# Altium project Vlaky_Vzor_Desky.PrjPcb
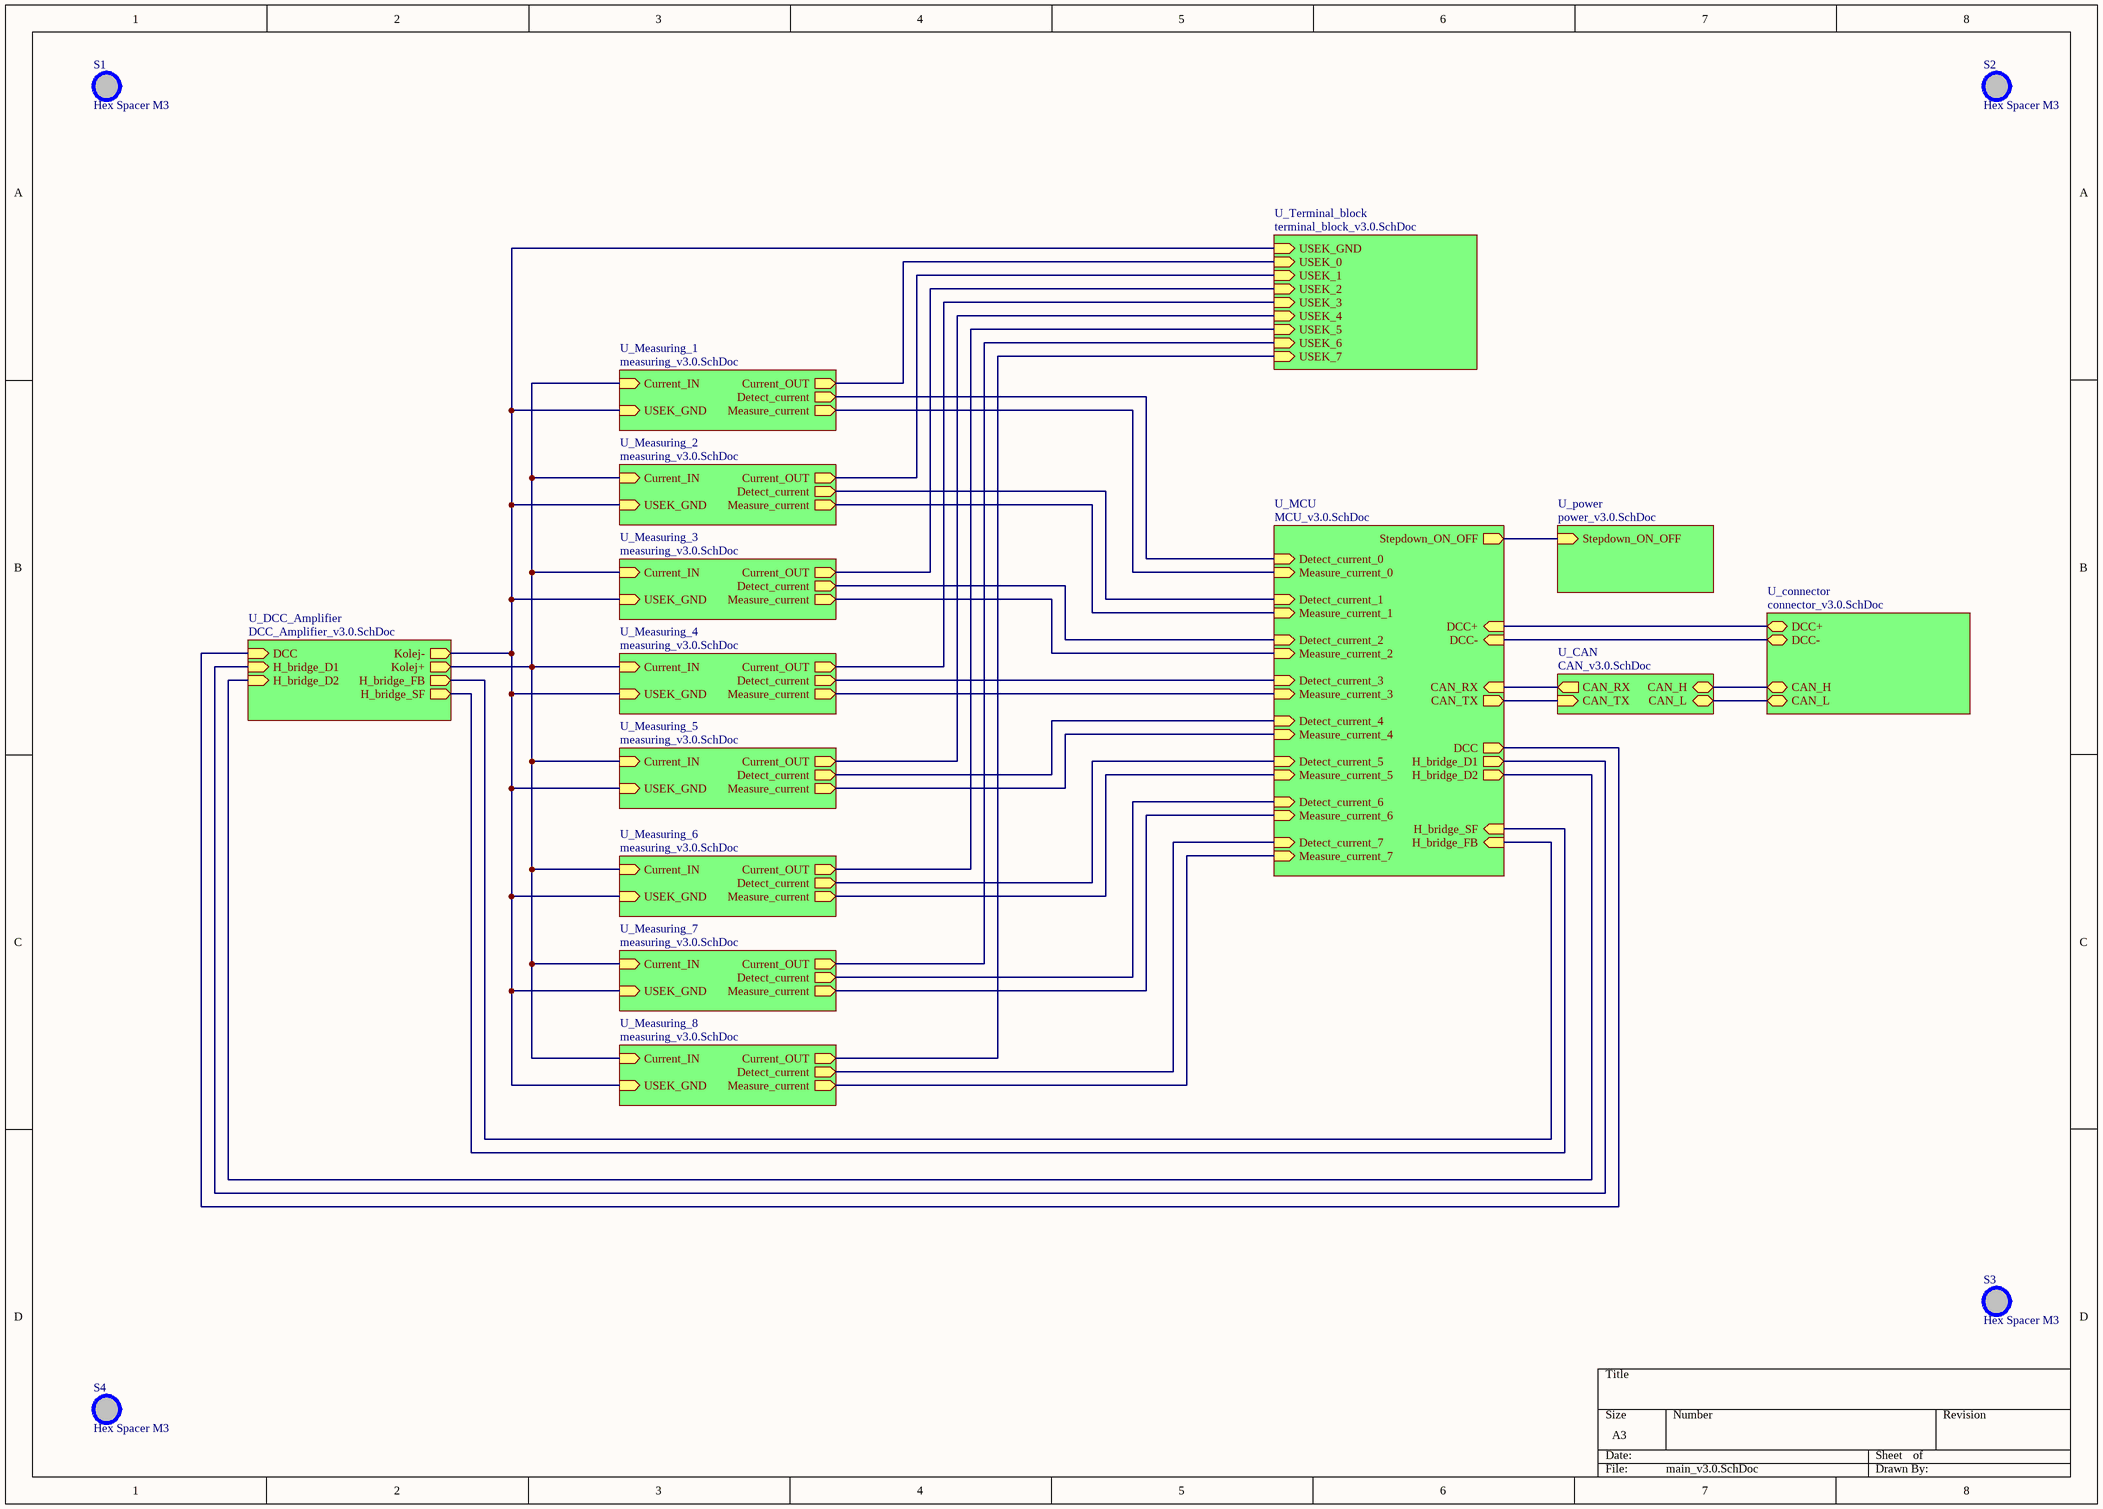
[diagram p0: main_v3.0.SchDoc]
10 sheets, 283 parts. Net scope: hierarchical (ports join the sheet entries above them; power ports are global).
Board file: PCB_v3.0.PcbDoc
Sheets:
  main_v3.0.SchDoc
    U_CAN = CAN_v3.0.SchDoc
    U_DCC_Amplifier = DCC_Amplifier_v3.0.SchDoc
    U_Terminal_block = terminal_block_v3.0.SchDoc
    U_MCU = MCU_v3.0.SchDoc
    U_power = power_v3.0.SchDoc
    U_connector = connector_v3.0.SchDoc
    U_Measuring_1 = measuring_v3.0.SchDoc
      U_Detect_current = detect_current_v3.0.SchDoc
      U_Measure_current = measure_current_v3.0.SchDoc
    U_Measuring_2 = measuring_v3.0.SchDoc
      U_Detect_current = detect_current_v3.0.SchDoc
      U_Measure_current = measure_current_v3.0.SchDoc
    U_Measuring_3 = measuring_v3.0.SchDoc
      U_Detect_current = detect_current_v3.0.SchDoc
      U_Measure_current = measure_current_v3.0.SchDoc
    U_Measuring_4 = measuring_v3.0.SchDoc
      U_Detect_current = detect_current_v3.0.SchDoc
      U_Measure_current = measure_current_v3.0.SchDoc
    U_Measuring_5 = measuring_v3.0.SchDoc
      U_Detect_current = detect_current_v3.0.SchDoc
      U_Measure_current = measure_current_v3.0.SchDoc
    U_Measuring_6 = measuring_v3.0.SchDoc
      U_Detect_current = detect_current_v3.0.SchDoc
      U_Measure_current = measure_current_v3.0.SchDoc
    U_Measuring_7 = measuring_v3.0.SchDoc
      U_Detect_current = detect_current_v3.0.SchDoc
      U_Measure_current = measure_current_v3.0.SchDoc
    U_Measuring_8 = measuring_v3.0.SchDoc
      U_Detect_current = detect_current_v3.0.SchDoc
      U_Measure_current = measure_current_v3.0.SchDoc

## Sheet main_v3.0.SchDoc
size A3; DocumentNumber: 1; SheetNumber: 1; SheetTotal: 10

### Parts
S1  Hex Spacer M3  [THT_HEX_SPACER_M3L20]
S2  Hex Spacer M3  [THT_HEX_SPACER_M3L20]
S3  Hex Spacer M3  [THT_HEX_SPACER_M3L20]
S4  Hex Spacer M3  [THT_HEX_SPACER_M3L20]

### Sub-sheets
U_CAN = CAN_v3.0.SchDoc: CAN_H (bidir), CAN_L (bidir), CAN_TX (in), CAN_RX (out)
U_connector = connector_v3.0.SchDoc: CAN_H (bidir), CAN_L (bidir), DCC+ (bidir), DCC- (bidir)
U_DCC_Amplifier = DCC_Amplifier_v3.0.SchDoc: DCC (in), Kolej- (out), Kolej+ (out), H_bridge_D1 (in), H_bridge_D2 (in), H_bridge_FB (out), H_bridge_SF (out)
U_MCU = MCU_v3.0.SchDoc: DCC- (in), DCC (out), Stepdown_ON_OFF (out), H_bridge_SF (in), H_bridge_D1 (out), H_bridge_D2 (out), H_bridge_FB (in), Measure_current_0 (in), Detect_current_0 (in), Detect_current_1 (in), DCC+ (in), CAN_TX (out), CAN_RX (in), Detect_current_2 (in), Detect_current_3 (in), Detect_current_4 (in), Detect_current_5 (in), Detect_current_6 (in), Detect_current_7 (in), Measure_current_1 (in), Measure_current_2 (in), Measure_current_3 (in), Measure_current_4 (in), Measure_current_5 (in), Measure_current_6 (in), Measure_current_7 (in)
U_Measuring_1 = measuring_v3.0.SchDoc: Current_IN (in), Measure_current (out), Detect_current (out), Current_OUT (out), USEK_GND (in)
U_Measuring_2 = measuring_v3.0.SchDoc: Current_IN (in), Measure_current (out), Detect_current (out), Current_OUT (out), USEK_GND (in)
U_Measuring_3 = measuring_v3.0.SchDoc: Current_IN (in), Measure_current (out), Detect_current (out), Current_OUT (out), USEK_GND (in)
U_Measuring_4 = measuring_v3.0.SchDoc: Current_IN (in), Measure_current (out), Detect_current (out), Current_OUT (out), USEK_GND (in)
U_Measuring_5 = measuring_v3.0.SchDoc: Current_IN (in), Measure_current (out), Detect_current (out), Current_OUT (out), USEK_GND (in)
U_Measuring_6 = measuring_v3.0.SchDoc: Current_IN (in), Measure_current (out), Detect_current (out), Current_OUT (out), USEK_GND (in)
U_Measuring_7 = measuring_v3.0.SchDoc: Current_IN (in), Measure_current (out), Detect_current (out), Current_OUT (out), USEK_GND (in)
U_Measuring_8 = measuring_v3.0.SchDoc: Current_IN (in), Measure_current (out), Detect_current (out), Current_OUT (out), USEK_GND (in)
U_power = power_v3.0.SchDoc: Stepdown_ON_OFF (in)
U_Terminal_block = terminal_block_v3.0.SchDoc: USEK_0 (in), USEK_GND (in), USEK_1 (in), USEK_2 (in), USEK_3 (in), USEK_4 (in), USEK_5 (in), USEK_6 (in), USEK_7 (in)

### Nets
CAN_H: sheet U_CAN/CAN_H, sheet U_connector/CAN_H
CAN_L: sheet U_CAN/CAN_L, sheet U_connector/CAN_L
CAN_RX: sheet U_CAN/CAN_RX, sheet U_MCU/CAN_RX
CAN_TX: sheet U_CAN/CAN_TX, sheet U_MCU/CAN_TX
DCC+: sheet U_MCU/DCC+, sheet U_connector/DCC+
DCC-: sheet U_MCU/DCC-, sheet U_connector/DCC-
NetC24.1_2: sheet U_DCC_Amplifier/Kolej-, sheet U_Terminal_block/USEK_GND, sheet U_Measuring_1/USEK_GND, sheet U_Measuring_2/USEK_GND, sheet U_Measuring_3/USEK_GND, sheet U_Measuring_4/USEK_GND, sheet U_Measuring_5/USEK_GND, sheet U_Measuring_6/USEK_GND, sheet U_Measuring_7/USEK_GND, sheet U_Measuring_8/USEK_GND
NetC27.1_2: sheet U_MCU/Measure_current_0, sheet U_Measuring_1/Measure_current
NetC27.2_2: sheet U_MCU/Measure_current_1, sheet U_Measuring_2/Measure_current
NetC27.3_2: sheet U_MCU/Measure_current_2, sheet U_Measuring_3/Measure_current
NetC27.4_2: sheet U_MCU/Measure_current_3, sheet U_Measuring_4/Measure_current
NetC27.5_2: sheet U_MCU/Measure_current_4, sheet U_Measuring_5/Measure_current
NetC27.6_2: sheet U_MCU/Measure_current_5, sheet U_Measuring_6/Measure_current
NetC27.7_2: sheet U_MCU/Measure_current_6, sheet U_Measuring_7/Measure_current
NetC27.8_2: sheet U_MCU/Measure_current_7, sheet U_Measuring_8/Measure_current
NetD12.1_2: sheet U_DCC_Amplifier/Kolej+, sheet U_Measuring_1/Current_IN, sheet U_Measuring_2/Current_IN, sheet U_Measuring_3/Current_IN, sheet U_Measuring_4/Current_IN, sheet U_Measuring_5/Current_IN, sheet U_Measuring_6/Current_IN, sheet U_Measuring_7/Current_IN, sheet U_Measuring_8/Current_IN
NetD17_1: sheet U_DCC_Amplifier/H_bridge_FB, sheet U_MCU/H_bridge_FB
NetIC1.1_3: sheet U_MCU/Detect_current_0, sheet U_Measuring_1/Detect_current
NetIC1.2_3: sheet U_MCU/Detect_current_1, sheet U_Measuring_2/Detect_current
NetIC1.3_3: sheet U_MCU/Detect_current_2, sheet U_Measuring_3/Detect_current
NetIC1.4_3: sheet U_MCU/Detect_current_3, sheet U_Measuring_4/Detect_current
NetIC1.5_3: sheet U_MCU/Detect_current_4, sheet U_Measuring_5/Detect_current
NetIC1.6_3: sheet U_MCU/Detect_current_5, sheet U_Measuring_6/Detect_current
NetIC1.7_3: sheet U_MCU/Detect_current_6, sheet U_Measuring_7/Detect_current
NetIC1.8_3: sheet U_MCU/Detect_current_7, sheet U_Measuring_8/Detect_current
NetP8_1: sheet U_Terminal_block/USEK_0, sheet U_Measuring_1/Current_OUT
NetP9_1: sheet U_Terminal_block/USEK_1, sheet U_Measuring_2/Current_OUT
NetP10_1: sheet U_Terminal_block/USEK_2, sheet U_Measuring_3/Current_OUT
NetP11_1: sheet U_Terminal_block/USEK_3, sheet U_Measuring_4/Current_OUT
NetP12_1: sheet U_Terminal_block/USEK_4, sheet U_Measuring_5/Current_OUT
NetP13_1: sheet U_Terminal_block/USEK_5, sheet U_Measuring_6/Current_OUT
NetP14_1: sheet U_Terminal_block/USEK_6, sheet U_Measuring_7/Current_OUT
NetP15_1: sheet U_Terminal_block/USEK_7, sheet U_Measuring_8/Current_OUT
NetR18_1: sheet U_DCC_Amplifier/H_bridge_D2, sheet U_MCU/H_bridge_D2
NetR22_2: sheet U_DCC_Amplifier/H_bridge_D1, sheet U_MCU/H_bridge_D1
NetR23_2: sheet U_MCU/Stepdown_ON_OFF, sheet U_power/Stepdown_ON_OFF
NetR32_1: sheet U_DCC_Amplifier/H_bridge_SF, sheet U_MCU/H_bridge_SF
NetU3_4: sheet U_DCC_Amplifier/DCC, sheet U_MCU/DCC

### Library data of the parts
S1-S4 = HEX_SPACER_M3: Hexagon metal spacer M3

## Sheet CAN_v3.0.SchDoc
size A4; DrawnBy: Lufinkao; DocumentNumber: 5; Revision: 11.4.2019; SheetNumber: 5; SheetTotal: 10
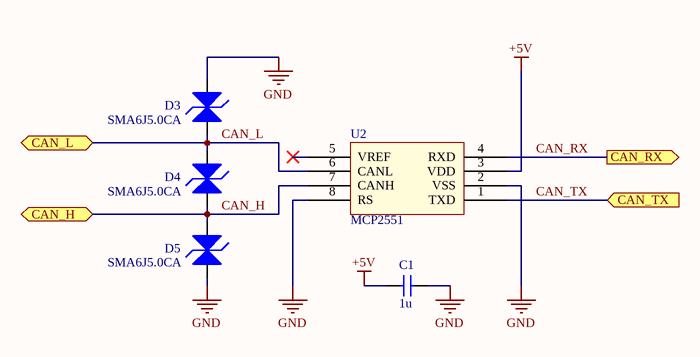
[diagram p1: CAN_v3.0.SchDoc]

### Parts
C1  1u  [SMD_CAPACITOR_0805]
D3  SMA6J5.0CA  [SMD_DO-214AC]
D4  SMA6J5.0CA  [SMD_DO-214AC]
D5  SMA6J5.0CA  [SMD_DO-214AC]
U2  MCP2551  [SMD_SOIC-8]

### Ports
CAN_H (bidir), CAN_L (bidir), CAN_RX (out), CAN_TX (in)

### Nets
+5V: C1.1 U2.3(VDD)
GND: C1.2 D3.2 D5.1 U2.2(VSS) U2.8(RS)
CAN_H: D4.1 D5.2 U2.7(CANH) ; port CAN_H
CAN_L: D3.1 D4.2 U2.6(CANL) ; port CAN_L
CAN_RX: U2.4(RXD) ; port CAN_RX
CAN_TX: U2.1(TXD) ; port CAN_TX

Not connected (* = marked no-connect by the designer): U2 5(VREF)*

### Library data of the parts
C1 = Capacitor
D3-D5 = Transil: Transient Voltage Suppressor, Bidirectional
U2 = MCP2551: CAN Transceiver, 4.5 V - 5.5 V, 1 Mb/s

## Sheet DCC_Amplifier_v3.0.SchDoc
size A3; DocumentNumber: 9; SheetNumber: 9; SheetTotal: 10
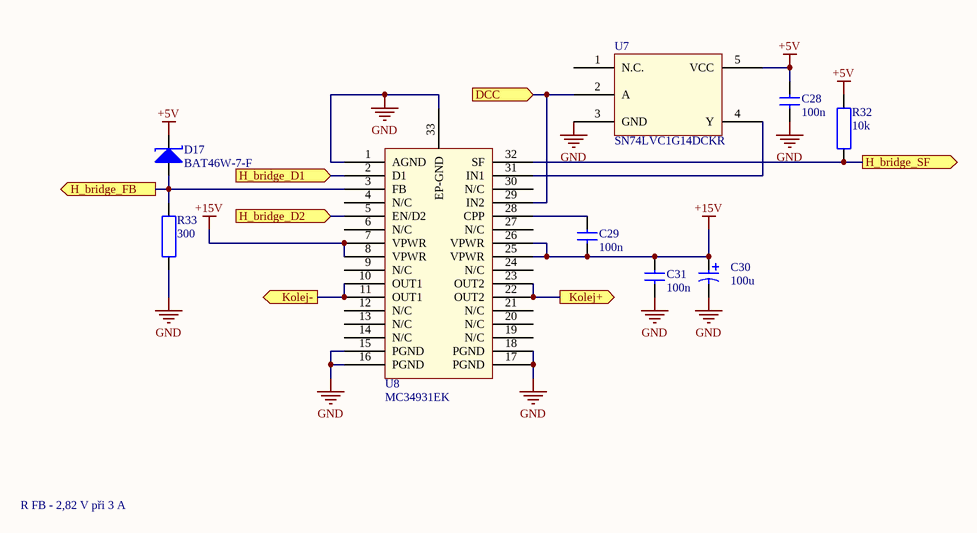
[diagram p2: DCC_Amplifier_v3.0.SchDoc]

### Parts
C28  100n  [SMD_CAPACITOR_0805]
C29  100n  [SMD_CAPACITOR_0805]
C30  100u  [SMD_CAPACITOR_D_6.3MM]
C31  100n  [SMD_CAPACITOR_0805]
D17  BAT46W-7-F  [SMD_SOD-123]
R32  10k  [SMD_RESISTOR_0805]
R33  300  [SMD_RESISTOR_0805]
U7  SN74LVC1G14DCKR  [SMD_SC-70-5]
U8  MC34931EK  [SMD_WSOIC32]

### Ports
DCC (in), H_bridge_D1 (in), H_bridge_D2 (in), H_bridge_FB (out), H_bridge_SF (out), Kolej+ (out), Kolej- (out)

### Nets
+5V: C28.2 D17.2 R32.2 U7.5(VCC)
+15V: C29.1 C30.1 C31.2 U8.7(VPWR) U8.8(VPWR) U8.25(VPWR) U8.26(VPWR)
GND: C28.1 C30.2 C31.1 R33.1 U7.3(GND) U8.1(AGND) U8.15(PGND) U8.16(PGND) U8.17(PGND) U8.18(PGND) U8.33(EP-GND)
NetC24.1_2: U8.10(OUT1) U8.11(OUT1) ; port Kolej-
NetC29_2: C29.2 U8.28(CPP)
NetD12.1_2: U8.22(OUT2) U8.23(OUT2) ; port Kolej+
NetD17_1: D17.1 R33.2 U8.3(FB) ; port H_bridge_FB
NetR18_1: U8.5(EN/D2) ; port H_bridge_D2
NetR22_2: U8.2(D1) ; port H_bridge_D1
NetR32_1: R32.1 U8.32(SF) ; port H_bridge_SF
NetU3_4: U7.2(A) U8.29(IN2) ; port DCC
NetU7_4: U7.4(Y) U8.31(IN1)

Not connected (* = marked no-connect by the designer): U7 1(N.C.); U8 4(N/C) 6(N/C) 9(N/C) 12(N/C) 13(N/C) 14(N/C) 19(N/C) 20(N/C) 21(N/C) 24(N/C) 27(N/C) 30(N/C)

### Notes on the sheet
- R FB - 2,82 V při 3 A

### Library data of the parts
C28 C29 C31 = Capacitor
C30 = Capacitor_POL
D17 = Diode_Schottky: Diode Schottky
R32 R33 = Resistor
U7 = SN74LVC1G14DCKR: Hradlo invertujici
U8 = MC34931EK: The MC34931EK is a monolithic H-bridge Power IC designed for any low voltage DC servo motor control application within the current and voltage limits stated in this specification.

## Sheet terminal_block_v3.0.SchDoc
size A3; DocumentNumber: 10; SheetNumber: 10; SheetTotal: 10
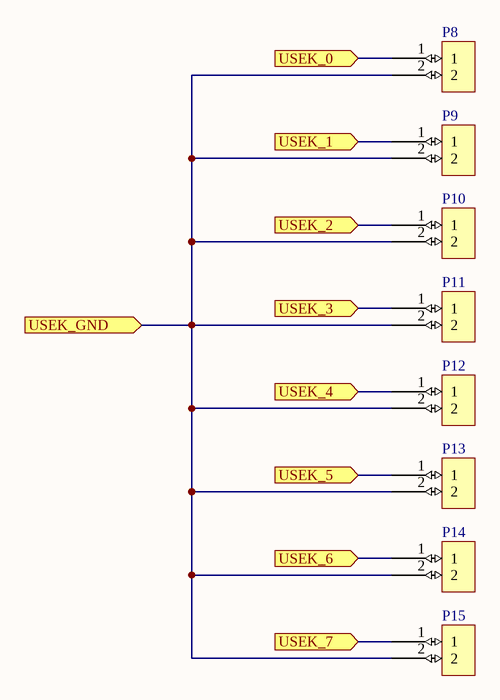
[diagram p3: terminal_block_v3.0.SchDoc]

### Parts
P8  End_Terminal_2pos_5.00mm  [Terminal_Block_2pos_5.00mm_pitch]  (value not drawn)
P9  End_Terminal_2pos_5.00mm  [Terminal_Block_2pos_5.00mm_pitch]  (value not drawn)
P10  End_Terminal_2pos_5.00mm  [Terminal_Block_2pos_5.00mm_pitch]  (value not drawn)
P11  End_Terminal_2pos_5.00mm  [Terminal_Block_2pos_5.00mm_pitch]  (value not drawn)
P12  End_Terminal_2pos_5.00mm  [Terminal_Block_2pos_5.00mm_pitch]  (value not drawn)
P13  End_Terminal_2pos_5.00mm  [Terminal_Block_2pos_5.00mm_pitch]  (value not drawn)
P14  End_Terminal_2pos_5.00mm  [Terminal_Block_2pos_5.00mm_pitch]  (value not drawn)
P15  End_Terminal_2pos_5.00mm  [Terminal_Block_2pos_5.00mm_pitch]  (value not drawn)

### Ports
USEK_0 (in), USEK_1 (in), USEK_2 (in), USEK_3 (in), USEK_4 (in), USEK_5 (in), USEK_6 (in), USEK_7 (in), USEK_GND (in)

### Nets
NetC24.1_2: P8.2 P9.2 P10.2 P11.2 P12.2 P13.2 P14.2 P15.2 ; port USEK_GND
NetP8_1: P8.1 ; port USEK_0
NetP9_1: P9.1 ; port USEK_1
NetP10_1: P10.1 ; port USEK_2
NetP11_1: P11.1 ; port USEK_3
NetP12_1: P12.1 ; port USEK_4
NetP13_1: P13.1 ; port USEK_5
NetP14_1: P14.1 ; port USEK_6
NetP15_1: P15.1 ; port USEK_7

## Sheet MCU_v3.0.SchDoc
size A4; DrawnBy: Lufinkao; DocumentNumber: 2; Revision: 11.4.2019; SheetNumber: 2; SheetTotal: 10
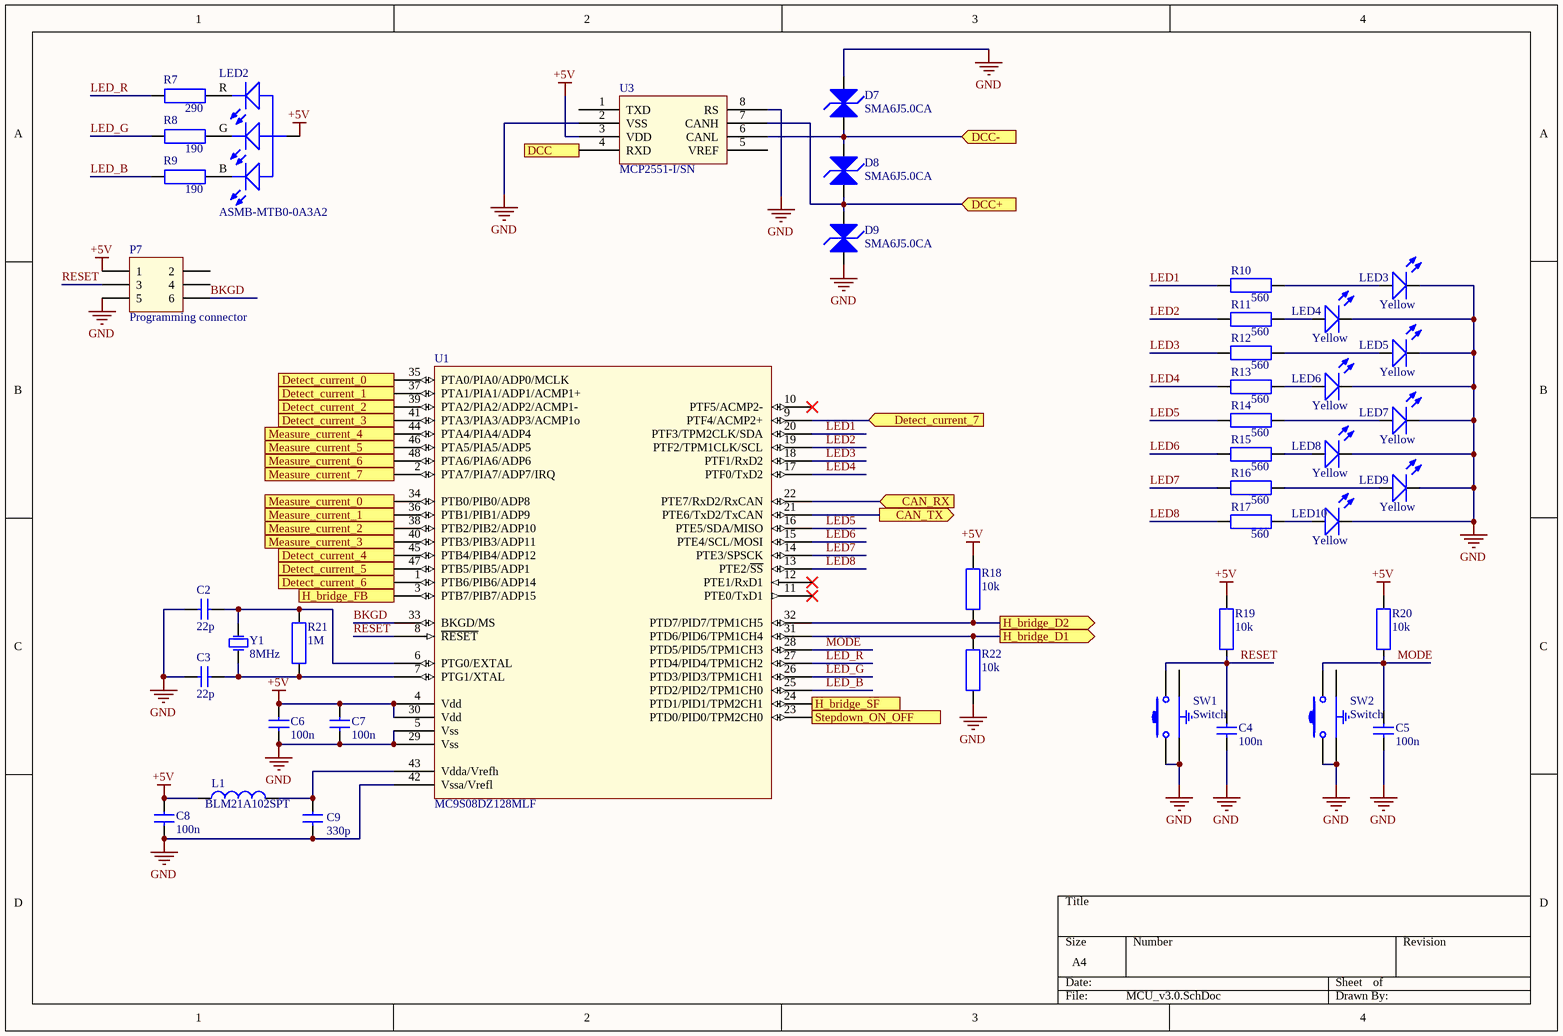
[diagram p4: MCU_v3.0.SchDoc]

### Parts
C2  22p  [SMD_CAPACITOR_0805]
C3  22p  [SMD_CAPACITOR_0805]
C4  100n  [SMD_CAPACITOR_0805]
C5  100n  [SMD_CAPACITOR_0805]
C6  100n  [SMD_CAPACITOR_0805]
C7  100n  [SMD_CAPACITOR_0805]
C8  100n  [SMD_CAPACITOR_0805]
C9  330p  [SMD_CAPACITOR_0805]
D7  SMA6J5.0CA  [SMD_DO-214AC]
D8  SMA6J5.0CA  [SMD_DO-214AC]
D9  SMA6J5.0CA  [SMD_DO-214AC]
L1  BLM21A102SPT  [SMD_INDUCTOR_0805]
LED2  ASMB-MTB0-0A3A2  [SMD_LED_RGB]
LED3  Yellow  [SMD_LED_0805]
LED4  Yellow  [SMD_LED_0805]
LED5  Yellow  [SMD_LED_0805]
LED6  Yellow  [SMD_LED_0805]
LED7  Yellow  [SMD_LED_0805]
LED8  Yellow  [SMD_LED_0805]
LED9  Yellow  [SMD_LED_0805]
LED10  Yellow  [SMD_LED_0805]
P7  Programming connector  [THT_HEADER_100MIL_2X3_MALE]
R7  290  [SMD_RESISTOR_0805]
R8  190  [SMD_RESISTOR_0805]
R9  190  [SMD_RESISTOR_0805]
R10  560  [SMD_RESISTOR_0805]
R11  560  [SMD_RESISTOR_0805]
R12  560  [SMD_RESISTOR_0805]
R13  560  [SMD_RESISTOR_0805]
R14  560  [SMD_RESISTOR_0805]
R15  560  [SMD_RESISTOR_0805]
R16  560  [SMD_RESISTOR_0805]
R17  560  [SMD_RESISTOR_0805]
R18  10k  [SMD_RESISTOR_0805]
R19  10k  [SMD_RESISTOR_0805]
R20  10k  [SMD_RESISTOR_0805]
R21  1M  [SMD_RESISTOR_0805]
R22  10k  [SMD_RESISTOR_0805]
SW1  Switch  [THT_SWITCH_SPST_90]
SW2  Switch  [THT_SWITCH_SPST_90]
U1  MC9S08DZ128MLF  [SMD_LQFP-48]
U3  MCP2551-I/SN  [SMD_SOIC-8]
Y1  8MHz  [SMD_XTAL_HC-49]

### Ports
CAN_RX (in), CAN_TX (out), DCC (out), DCC+ (in), DCC- (in), Detect_current_0 (in), Detect_current_1 (in), Detect_current_2 (in), Detect_current_3 (in), Detect_current_4 (in), Detect_current_5 (in), Detect_current_6 (in), Detect_current_7 (in), H_bridge_D1 (out), H_bridge_D2 (out), H_bridge_FB (in), H_bridge_SF (in), Measure_current_0 (in), Measure_current_1 (in), Measure_current_2 (in), Measure_current_3 (in), Measure_current_4 (in), Measure_current_5 (in), Measure_current_6 (in), Measure_current_7 (in), Stepdown_ON_OFF (out)

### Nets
+5V: C6.1 C7.1 C8.1 L1.1 LED2.1(ANODE) P7.1 R18.2 R19.2 R20.2 U1.4(Vdd) U1.30(Vdd) U3.3(VDD)
GND: C2.1 C3.1 C4.2 C5.2 C6.2 C7.2 C8.2 C9.1 D7.2 D9.1 LED3.2 LED4.2 LED5.2 LED6.2 LED7.2 LED8.2 LED9.2 LED10.2 P7.5 R22.1 SW1.1 SW1.3 SW2.1 SW2.3 U1.5(Vss) U1.29(Vss) U1.42(Vssa/Vrefl) U3.2(VSS) U3.8(RS)
BKGD: P7.6 U1.33(BKGD/MS)
CAN_RX: U1.22(PTE7/RxD2/RxCAN) ; port CAN_RX
CAN_TX: U1.21(PTE6/TxD2/TxCAN) ; port CAN_TX
DCC+: D8.1 D9.2 U3.7(CANH) ; port DCC+
DCC-: D7.1 D8.2 U3.6(CANL) ; port DCC-
LED1: R10.1 U1.20(PTF3/TPM2CLK/SDA)
LED2: R11.1 U1.19(PTF2/TPM1CLK/SCL)
LED3: R12.1 U1.18(PTF1/RxD2)
LED4: R13.1 U1.17(PTF0/TxD2)
LED5: R14.1 U1.16(PTE5/SDA/MISO)
LED6: R15.1 U1.15(PTE4/SCL/MOSI)
LED7: R16.1 U1.14(PTE3/SPSCK)
LED8: R17.1 U1.13(PTE2/~{SS})
LED_B: R9.2 U1.25(PTD2/PID2/TPM1CH0)
LED_G: R8.2 U1.26(PTD3/PID3/TPM1CH1)
LED_R: R7.2 U1.27(PTD4/PID4/TPM1CH2)
MODE: C5.1 R20.1 SW2.2 U1.28(PTD5/PID5/TPM1CH3)
RESET: C4.1 P7.3 R19.1 SW1.2 U1.8(~{RESET})
NetC2_2: C2.2 R21.2 U1.6(PTG0/EXTAL) Y1.2
NetC3_2: C3.2 R21.1 U1.7(PTG1/XTAL) Y1.1
NetC9_2: C9.2 L1.2 U1.43(Vdda/Vrefh)
NetC27.1_2: U1.34(PTB0/PIB0/ADP8) ; port Measure_current_0
NetC27.2_2: U1.36(PTB1/PIB1/ADP9) ; port Measure_current_1
NetC27.3_2: U1.38(PTB2/PIB2/ADP10) ; port Measure_current_2
NetC27.4_2: U1.40(PTB3/PIB3/ADP11) ; port Measure_current_3
NetC27.5_2: U1.44(PTA4/PIA4/ADP4) ; port Measure_current_4
NetC27.6_2: U1.46(PTA5/PIA5/ADP5) ; port Measure_current_5
NetC27.7_2: U1.48(PTA6/PIA6/ADP6) ; port Measure_current_6
NetC27.8_2: U1.2(PTA7/PIA7/ADP7/IRQ) ; port Measure_current_7
NetD17_1: U1.3(PTB7/PIB7/ADP15) ; port H_bridge_FB
NetIC1.1_3: U1.35(PTA0/PIA0/ADP0/MCLK) ; port Detect_current_0
NetIC1.2_3: U1.37(PTA1/PIA1/ADP1/ACMP1+) ; port Detect_current_1
NetIC1.3_3: U1.39(PTA2/PIA2/ADP2/ACMP1-) ; port Detect_current_2
NetIC1.4_3: U1.41(PTA3/PIA3/ADP3/ACMP1o) ; port Detect_current_3
NetIC1.5_3: U1.45(PTB4/PIB4/ADP12) ; port Detect_current_4
NetIC1.6_3: U1.47(PTB5/PIB5/ADP1) ; port Detect_current_5
NetIC1.7_3: U1.1(PTB6/PIB6/ADP14) ; port Detect_current_6
NetIC1.8_3: U1.9(PTF4/ACMP2+) ; port Detect_current_7
NetLED2_2: LED2.2(B) R9.1
NetLED2_3: LED2.3(G) R8.1
NetLED2_4: LED2.4(R) R7.1
NetLED3_1: LED3.1 R10.2
NetLED4_1: LED4.1 R11.2
NetLED5_1: LED5.1 R12.2
NetLED6_1: LED6.1 R13.2
NetLED7_1: LED7.1 R14.2
NetLED8_1: LED8.1 R15.2
NetLED9_1: LED9.1 R16.2
NetLED10_1: LED10.1 R17.2
NetR18_1: R18.1 U1.32(PTD7/PID7/TPM1CH5) ; port H_bridge_D2
NetR22_2: R22.2 U1.31(PTD6/PID6/TPM1CH4) ; port H_bridge_D1
NetR23_2: U1.23(PTD0/PID0/TPM2CH0) ; port Stepdown_ON_OFF
NetR32_1: U1.24(PTD1/PID1/TPM2CH1) ; port H_bridge_SF
NetU3_4: U3.4(RXD) ; port DCC

Not connected (* = marked no-connect by the designer): P7 2 4; SW1 4; SW2 4; U1 10(PTF5/ACMP2-)* 11(PTE0/TxD1)* 12(PTE1/RxD1)*; U3 1(TXD) 5(VREF)

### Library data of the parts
C2-C9 = Capacitor
D7-D9 = Transil: as D3 on sheet CAN_v3.0
L1 = Inductor
LED2 = LED_RGB: LED RGB
LED3-LED10 = LED
P7 = Header_2x3: Header 2x3
R7-R22 = Resistor
SW1 SW2 = Switch_90: Tactile Switch Right Angle
U1 = MC9S08DZ96: NXP 8 Bit Microcontroller, CAN
U3 = MCP2551: CAN Transceiver, 4.5 V - 5.5 V, 1 Mb/s
Y1 = XTAL: Crystal Oscillator

## Sheet power_v3.0.SchDoc
size A4; DrawnBy: Lufinkao; DocumentNumber: 4; Revision: 11.4.2019; SheetNumber: 4; SheetTotal: 10
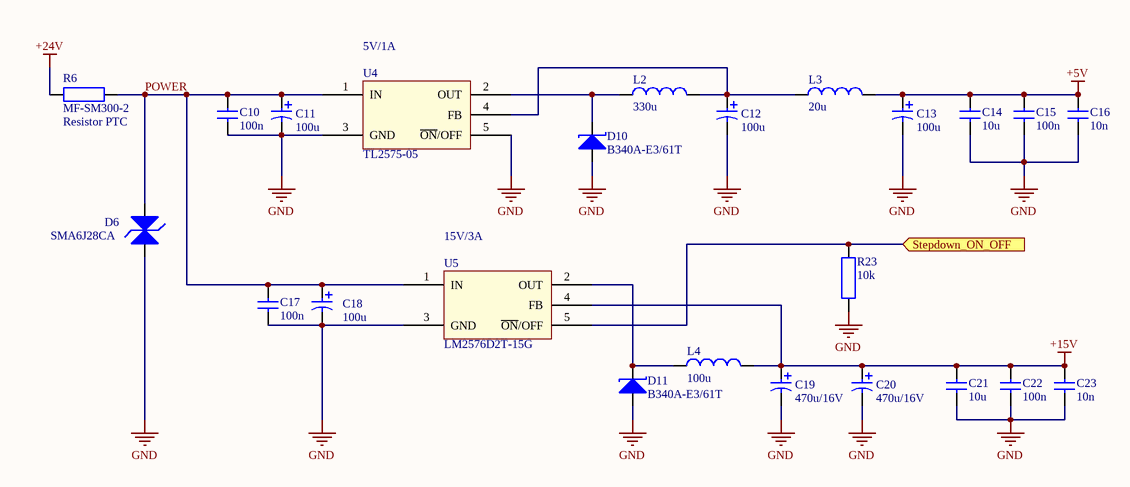
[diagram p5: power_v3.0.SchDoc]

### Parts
C10  value 100n  [SMD_CAPACITOR_0805]  (hidden comment: 10u)
C11  100u  [SMD_CAPACITOR_D_6.3MM]
C12  100u  [SMD_CAPACITOR_D_6.3MM]
C13  100u  [SMD_CAPACITOR_D_6.3MM]
C14  10u  [SMD_CAPACITOR_0805]
C15  100n  [SMD_CAPACITOR_0805]
C16  10n  [SMD_CAPACITOR_0805]
C17  value 100n  [SMD_CAPACITOR_0805]  (hidden comment: 10n)
C18  100u  [SMD_CAPACITOR_D_6.3MM]
C19  470u/16V  [SMD_CAPACITOR_D_10MM]
C20  470u/16V  [SMD_CAPACITOR_D_10MM]
C21  10u  [SMD_CAPACITOR_0805]
C22  100n  [SMD_CAPACITOR_0805]
C23  10n  [SMD_CAPACITOR_0805]
D6  SMA6J28CA  [SMD_DO-214AC]
D10  B340A-E3/61T  [SMD_DO-214AC]
D11  B340A-E3/61T  [SMD_DO-214AC]
L2  330u  [SMD_INDUCTOR_12.5MM]
L3  20u  [SMD_INDUCTOR_7.3MM]
L4  100u  [SMD_INDUCTOR_12.5MM]
R6  MF-SM300-2  [SMD_RESISTOR_PTC_MF-SM]
R23  10k  [SMD_RESISTOR_0805]
U4  TL2575-05  [SMD_TO-263-5]
U5  LM2576D2T-15G  [SMD_TO-263-5]

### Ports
Stepdown_ON_OFF (in)

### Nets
+5V: C13.1 C14.2 C15.2 C16.2 L3.2
+15V: C19.1 C20.1 C21.2 C22.2 C23.2 L4.2 U5.4(FB)
+24V: R6.1
GND: C10.1 C11.2 C12.2 C13.2 C14.1 C15.1 C16.1 C17.1 C18.2 C19.2 C20.2 C21.1 C22.1 C23.1 D6.1 D10.1 D11.1 R23.1 U4.3(GND) U4.5(~{ON}/OFF) U5.3(GND)
POWER: C10.2 C11.1 C17.2 C18.1 D6.2 R6.2 U4.1(IN) U5.1(IN)
NetC12_1: C12.1 L2.2 L3.1 U4.4(FB)
NetD10_2: D10.2 L2.1 U4.2(OUT)
NetD11_2: D11.2 L4.1 U5.2(OUT)
NetR23_2: R23.2 U5.5(~{ON}/OFF) ; port Stepdown_ON_OFF

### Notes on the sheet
- (near U4) 5V/1A
- (near U5) 15V/3A

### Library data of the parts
C10 C14-C17 C21-C23 = Capacitor
C11-C13 C18-C20 = Capacitor_POL
D6 = Transil: as D3 on sheet CAN_v3.0
D10 D11 = Diode_Schottky: Diode Schottky
L2-L4 = Inductor
R6 = Resistor_PTC: Resistor PTC
R23 = Resistor
U4 U5 = TL2575-05: Buck (Step Down) Switching Regulator, 4.75V-40V Input, 5 V, 1A Output

## Sheet connector_v3.0.SchDoc
size A4; DrawnBy: Lufinkao; DocumentNumber: 3; Revision: 11.4.2019; SheetNumber: 3; SheetTotal: 10
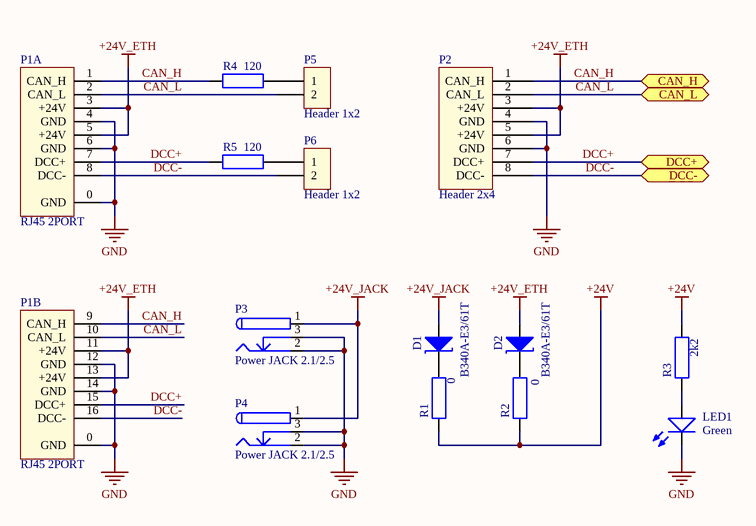
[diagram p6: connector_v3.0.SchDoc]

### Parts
D1  B340A-E3/61T  [SMD_DO-214AC]
D2  B340A-E3/61T  [SMD_DO-214AC]
LED1  Green  [THT_LED_3MM]
P1  RJ45 2PORT  [THT_RJ45_2PORT]  (parts A,B of 2)
P2  Header 2x4  [SMD_HEADER_100MIL_2X4_DOUBLESIDED]
P3  Power JACK 2.1/2.5  [THT_POWER_JACK_2.1/2.5]
P4  Power JACK 2.1/2.5  [THT_POWER_JACK_2.1/2.5]
P5  Header 1x2  [THT_HEADER_100MIL_1X2_MALE]
P6  Header 1x2  [THT_HEADER_100MIL_1X2_MALE]
R1  0  [SMD_RESISTOR_0805]
R2  0  [SMD_RESISTOR_0805]
R3  2k2  [SMD_RESISTOR_0805]
R4  120  [SMD_RESISTOR_0805]
R5  120  [SMD_RESISTOR_0805]

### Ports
CAN_H (bidir), CAN_L (bidir), DCC+ (bidir), DCC- (bidir)

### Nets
+24V: R1.1 R2.1 R3.2
+24V_ETH: D2.1 P1.3(+24V) P1.5(+24V) P1.11(+24V) P1.13(+24V) P2.3(+24V) P2.5(+24V)
+24V_JACK: D1.1 P3.1 P4.1
GND: LED1.2 P1.0(GND) P1.4(GND) P1.6(GND) P1.12(GND) P1.14(GND) P2.4(GND) P2.6(GND) P3.2 P3.3 P4.2 P4.3
CAN_H: P1.1(CAN_H) P1.9(CAN_H) P2.1(CAN_H) R4.2 ; port CAN_H
CAN_L: P1.2(CAN_L) P1.10(CAN_L) P2.2(CAN_L) P5.2 ; port CAN_L
DCC+: P1.7(DCC+) P1.15(DCC+) P2.7(DCC+) R5.2 ; port DCC+
DCC-: P1.8(DCC-) P1.16(DCC-) P2.8(DCC-) P6.2 ; port DCC-
NetD1_2: D1.2 R1.2
NetD2_2: D2.2 R2.2
NetLED1_1: LED1.1 R3.1
NetP5_1: P5.1 R4.1
NetP6_1: P6.1 R5.1

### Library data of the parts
D1 D2 = Diode_Schottky: Diode Schottky
LED1 = LED
P1 = RJ45_2PORT: RJ45 - 2 port; Objednací kód: RJHSE538002; Dodavatel: TME; Výrobce: AMPHENOL
P2 = Header_2x4_Trains_Project
P3 P4 = Power_JACK_2.1/2.5: Low Voltage Power Supply Connector
P5 P6 = Header_1x2
R1-R5 = Resistor

## Sheet measuring_v3.0.SchDoc
size A3; DocumentNumber: 6; SheetNumber: 6; SheetTotal: 8
Used 8 times, as channels U_Measuring_1, U_Measuring_2, U_Measuring_3, U_Measuring_4, U_Measuring_5, U_Measuring_6, U_Measuring_7, U_Measuring_8. Parts and nets are listed once, with the designators drawn on the sheet.
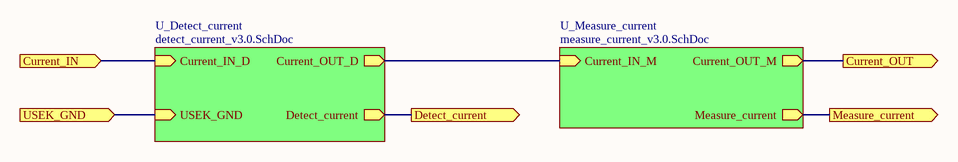
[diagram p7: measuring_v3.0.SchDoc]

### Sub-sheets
U_Detect_current = detect_current_v3.0.SchDoc: Current_IN_D (in), Current_OUT_D (out), Detect_current (out), USEK_GND (in)
U_Measure_current = measure_current_v3.0.SchDoc: Current_IN_M (in), Measure_current (out), Current_OUT_M (out)

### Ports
Current_IN (in), Current_OUT (out), Detect_current (out), Measure_current (out), USEK_GND (in)

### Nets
Current_IN: port Current_IN, sheet U_Detect_current/Current_IN_D
Current_OUT: port Current_OUT, sheet U_Measure_current/Current_OUT_M
Detect_current: port Detect_current, sheet U_Detect_current/Detect_current
Measure_current: port Measure_current, sheet U_Measure_current/Measure_current
USEK_GND: port USEK_GND, sheet U_Detect_current/USEK_GND
(unnamed): sheet U_Detect_current/Current_OUT_D, sheet U_Measure_current/Current_IN_M

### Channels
U_Measuring_1: ports Current_IN=NetD12.1_2 Current_OUT=NetP8_1 Detect_current=NetIC1.1_3 Measure_current=NetC27.1_2 USEK_GND=NetC24.1_2
U_Measuring_2: ports Current_IN=NetD12.1_2 Current_OUT=NetP9_1 Detect_current=NetIC1.2_3 Measure_current=NetC27.2_2 USEK_GND=NetC24.1_2
U_Measuring_3: ports Current_IN=NetD12.1_2 Current_OUT=NetP10_1 Detect_current=NetIC1.3_3 Measure_current=NetC27.3_2 USEK_GND=NetC24.1_2
U_Measuring_4: ports Current_IN=NetD12.1_2 Current_OUT=NetP11_1 Detect_current=NetIC1.4_3 Measure_current=NetC27.4_2 USEK_GND=NetC24.1_2
U_Measuring_5: ports Current_IN=NetD12.1_2 Current_OUT=NetP12_1 Detect_current=NetIC1.5_3 Measure_current=NetC27.5_2 USEK_GND=NetC24.1_2
U_Measuring_6: ports Current_IN=NetD12.1_2 Current_OUT=NetP13_1 Detect_current=NetIC1.6_3 Measure_current=NetC27.6_2 USEK_GND=NetC24.1_2
U_Measuring_7: ports Current_IN=NetD12.1_2 Current_OUT=NetP14_1 Detect_current=NetIC1.7_3 Measure_current=NetC27.7_2 USEK_GND=NetC24.1_2
U_Measuring_8: ports Current_IN=NetD12.1_2 Current_OUT=NetP15_1 Detect_current=NetIC1.8_3 Measure_current=NetC27.8_2 USEK_GND=NetC24.1_2

## Sheet detect_current_v3.0.SchDoc
size A3; DocumentNumber: 7; SheetNumber: 7; SheetTotal: 8
Used 8 times, as channels U_Measuring_1/U_Detect_current, U_Measuring_2/U_Detect_current, U_Measuring_3/U_Detect_current, U_Measuring_4/U_Detect_current, U_Measuring_5/U_Detect_current, U_Measuring_6/U_Detect_current, U_Measuring_7/U_Detect_current, U_Measuring_8/U_Detect_current. Parts and nets are listed once, with the designators drawn on the sheet.
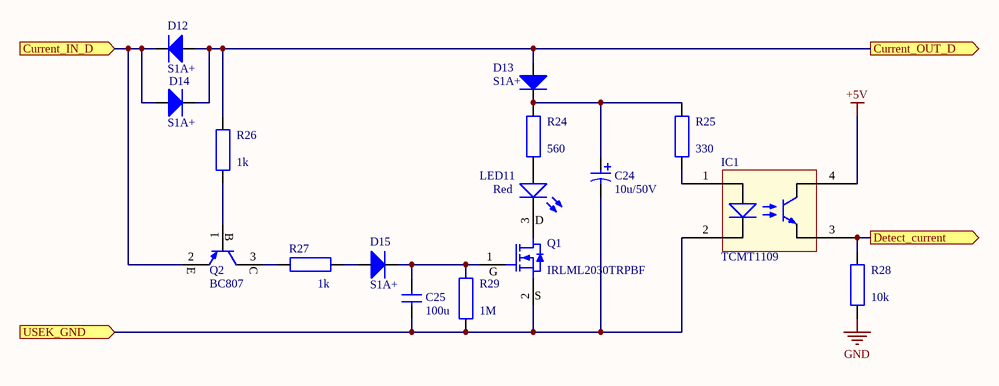
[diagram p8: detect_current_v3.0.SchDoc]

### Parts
C24  10u/50V  [SMD_CAPACITOR_D_6.3MM]
C25  100u  [SMD_CAPACITOR_0805]
D12  S1A+  [SMD_DO-214AC]
D13  S1A+  [SMD_DO-214AC]
D14  S1A+  [SMD_DO-214AC]
D15  S1A+  [SMD_DO-214AC]
IC1  TCMT1109  [TCMT110x]
LED11  Red  [SMD_LED_0805]
Q1  IRLML2030TRPBF  [SMD_SOT-23]
Q2  BC807  [SMD_SOT-23]
R24  560  [SMD_RESISTOR_0805]
R25  330  [SMD_RESISTOR_0805]
R26  1k  [SMD_RESISTOR_0805]
R27  1k  [SMD_RESISTOR_0805]
R28  10k  [SMD_RESISTOR_0805]
R29  1M  [SMD_RESISTOR_0805]

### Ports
Current_IN_D (in), Current_OUT_D (out), Detect_current (out), USEK_GND (in)

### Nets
+5V: IC1.4
GND: R28.1
Current_IN_D: D12.2 D14.1 Q2.2 ; port Current_IN_D
Current_OUT_D: D12.1 D13.1 D14.2 R26.2 ; port Current_OUT_D
Detect_current: IC1.3 R28.2 ; port Detect_current
USEK_GND: C24.2 C25.1 IC1.2 Q1.2 R29.1 ; port USEK_GND
NetC24_1: C24.1 D13.2 R24.2 R25.1
NetC25_2: C25.2 D15.2 Q1.1 R29.2
NetD15_1: D15.1 R27.1
NetIC1_1: IC1.1 R25.2
NetLED11_1: LED11.1 R24.1
NetLED11_2: LED11.2 Q1.3
NetQ2_1: Q2.1 R26.1
NetQ2_3: Q2.3 R27.2

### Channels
U_Measuring_1/U_Detect_current: designators C24=C24.1 C25=C25.1 D12=D12.1 D13=D13.1 D14=D14.1 D15=D15.1 IC1=IC1.1 LED11=LED11.1 Q1=Q1.1 Q2=Q2.1 R24=R25.1 R25=R26.1 R26=R27.1 R27=R28.1 R28=R29.1 R29=R30.1; ports Current_IN_D=NetD12.1_2 Current_OUT_D=NetD12.1_1 Detect_current=NetIC1.1_3 USEK_GND=NetC24.1_2
U_Measuring_2/U_Detect_current: designators C24=C24.2 C25=C25.2 D12=D12.2 D13=D13.2 D14=D14.2 D15=D15.2 IC1=IC1.2 LED11=LED11.2 Q1=Q1.2 Q2=Q2.2 R24=R25.2 R25=R26.2 R26=R27.2 R27=R28.2 R28=R29.2 R29=R30.2; ports Current_IN_D=NetD12.1_2 Current_OUT_D=NetD12.2_1 Detect_current=NetIC1.2_3 USEK_GND=NetC24.1_2
U_Measuring_3/U_Detect_current: designators C24=C24.3 C25=C25.3 D12=D12.3 D13=D13.3 D14=D14.3 D15=D15.3 IC1=IC1.3 LED11=LED11.3 Q1=Q1.3 Q2=Q2.3 R24=R25.3 R25=R26.3 R26=R27.3 R27=R28.3 R28=R29.3 R29=R30.3; ports Current_IN_D=NetD12.1_2 Current_OUT_D=NetD12.3_1 Detect_current=NetIC1.3_3 USEK_GND=NetC24.1_2
U_Measuring_4/U_Detect_current: designators C24=C24.4 C25=C25.4 D12=D12.4 D13=D13.4 D14=D14.4 D15=D15.4 IC1=IC1.4 LED11=LED11.4 Q1=Q1.4 Q2=Q2.4 R24=R25.4 R25=R26.4 R26=R27.4 R27=R28.4 R28=R29.4 R29=R30.4; ports Current_IN_D=NetD12.1_2 Current_OUT_D=NetD12.4_1 Detect_current=NetIC1.4_3 USEK_GND=NetC24.1_2
U_Measuring_5/U_Detect_current: designators C24=C24.5 C25=C25.5 D12=D12.5 D13=D13.5 D14=D14.5 D15=D15.5 IC1=IC1.5 LED11=LED11.5 Q1=Q1.5 Q2=Q2.5 R24=R25.5 R25=R26.5 R26=R27.5 R27=R28.5 R28=R29.5 R29=R30.5; ports Current_IN_D=NetD12.1_2 Current_OUT_D=NetD12.5_1 Detect_current=NetIC1.5_3 USEK_GND=NetC24.1_2
U_Measuring_6/U_Detect_current: designators C24=C24.6 C25=C25.6 D12=D12.6 D13=D13.6 D14=D14.6 D15=D15.6 IC1=IC1.6 LED11=LED11.6 Q1=Q1.6 Q2=Q2.6 R24=R25.6 R25=R26.6 R26=R27.6 R27=R28.6 R28=R29.6 R29=R30.6; ports Current_IN_D=NetD12.1_2 Current_OUT_D=NetD12.6_1 Detect_current=NetIC1.6_3 USEK_GND=NetC24.1_2
U_Measuring_7/U_Detect_current: designators C24=C24.7 C25=C25.7 D12=D12.7 D13=D13.7 D14=D14.7 D15=D15.7 IC1=IC1.7 LED11=LED11.7 Q1=Q1.7 Q2=Q2.7 R24=R25.7 R25=R26.7 R26=R27.7 R27=R28.7 R28=R29.7 R29=R30.7; ports Current_IN_D=NetD12.1_2 Current_OUT_D=NetD12.7_1 Detect_current=NetIC1.7_3 USEK_GND=NetC24.1_2
U_Measuring_8/U_Detect_current: designators C24=C24.8 C25=C25.8 D12=D12.8 D13=D13.8 D14=D14.8 D15=D15.8 IC1=IC1.8 LED11=LED11.8 Q1=Q1.8 Q2=Q2.8 R24=R25.8 R25=R26.8 R26=R27.8 R27=R28.8 R28=R29.8 R29=R30.8; ports Current_IN_D=NetD12.1_2 Current_OUT_D=NetD12.8_1 Detect_current=NetIC1.8_3 USEK_GND=NetC24.1_2

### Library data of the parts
C24 = Capacitor_POL
C25 = Capacitor
D12-D15 = Diode: Diode_S1A+
IC1 = TCMT1109: optočlen
LED11 = LED
Q1 = Transistor_MOSFET_N: Transistor MOSFET N
Q2 = BC807: Transistor PNP; Suplier: Farnell; SupOrderNumber: 1081220
R24-R29 = Resistor

## Sheet measure_current_v3.0.SchDoc
size A3; DocumentNumber: 8; SheetNumber: 8; SheetTotal: 10
Used 8 times, as channels U_Measuring_1/U_Measure_current, U_Measuring_2/U_Measure_current, U_Measuring_3/U_Measure_current, U_Measuring_4/U_Measure_current, U_Measuring_5/U_Measure_current, U_Measuring_6/U_Measure_current, U_Measuring_7/U_Measure_current, U_Measuring_8/U_Measure_current. Parts and nets are listed once, with the designators drawn on the sheet.
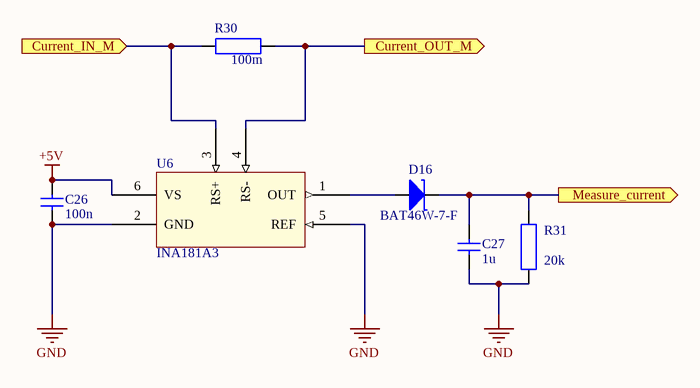
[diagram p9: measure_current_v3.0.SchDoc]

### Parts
C26  100n  [SMD_CAPACITOR_0805]
C27  1u  [SMD_CAPACITOR_0805]
D16  BAT46W-7-F  [SMD_SOD-123]
R30  100m  [Resistor]
R31  20k  [SMD_RESISTOR_0805]
U6  value INA181A3  [SMD_SOT-23-6]  (hidden comment: INA181)

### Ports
Current_IN_M (in), Current_OUT_M (out), Measure_current (out)

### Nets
+5V: C26.2 U6.6(VS)
GND: C26.1 C27.1 R31.1 U6.2(GND) U6.5(REF)
Current_IN_M: R30.1 U6.3(RS+) ; port Current_IN_M
Current_OUT_M: R30.2 U6.4(RS-) ; port Current_OUT_M
Measure_current: C27.2 D16.2 R31.2 ; port Measure_current
NetD16_1: D16.1 U6.1(OUT)

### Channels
U_Measuring_1/U_Measure_current: designators C26=C26.1 C27=C27.1 D16=D16.1 R30=R31.1 R31=R32.1 U6=U6.1; ports Current_IN_M=NetD12.1_1 Current_OUT_M=NetP8_1 Measure_current=NetC27.1_2
U_Measuring_2/U_Measure_current: designators C26=C26.2 C27=C27.2 D16=D16.2 R30=R31.2 R31=R32.2 U6=U6.2; ports Current_IN_M=NetD12.2_1 Current_OUT_M=NetP9_1 Measure_current=NetC27.2_2
U_Measuring_3/U_Measure_current: designators C26=C26.3 C27=C27.3 D16=D16.3 R30=R31.3 R31=R32.3 U6=U6.3; ports Current_IN_M=NetD12.3_1 Current_OUT_M=NetP10_1 Measure_current=NetC27.3_2
U_Measuring_4/U_Measure_current: designators C26=C26.4 C27=C27.4 D16=D16.4 R30=R31.4 R31=R32.4 U6=U6.4; ports Current_IN_M=NetD12.4_1 Current_OUT_M=NetP11_1 Measure_current=NetC27.4_2
U_Measuring_5/U_Measure_current: designators C26=C26.5 C27=C27.5 D16=D16.5 R30=R31.5 R31=R32.5 U6=U6.5; ports Current_IN_M=NetD12.5_1 Current_OUT_M=NetP12_1 Measure_current=NetC27.5_2
U_Measuring_6/U_Measure_current: designators C26=C26.6 C27=C27.6 D16=D16.6 R30=R31.6 R31=R32.6 U6=U6.6; ports Current_IN_M=NetD12.6_1 Current_OUT_M=NetP13_1 Measure_current=NetC27.6_2
U_Measuring_7/U_Measure_current: designators C26=C26.7 C27=C27.7 D16=D16.7 R30=R31.7 R31=R32.7 U6=U6.7; ports Current_IN_M=NetD12.7_1 Current_OUT_M=NetP14_1 Measure_current=NetC27.7_2
U_Measuring_8/U_Measure_current: designators C26=C26.8 C27=C27.8 D16=D16.8 R30=R31.8 R31=R32.8 U6=U6.8; ports Current_IN_M=NetD12.8_1 Current_OUT_M=NetP15_1 Measure_current=NetC27.8_2

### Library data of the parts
C26 C27 = Capacitor
D16 = Diode_Schottky: Diode Schottky
R30 = Resistor_2512
R31 = Resistor
U6 = INA181: Current sense amplifiers are designed for costoptimized  applications.

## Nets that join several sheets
+5V: CAN_v3.0 (C1.1 U2.3), DCC_Amplifier_v3.0 (C28.2 D17.2 R32.2 U7.5), MCU_v3.0 (12 pins), power_v3.0 (5 pins), U_Measuring_1/U_Detect_current (IC1.1.4), U_Measuring_1/U_Measure_current (C26.1.2 U6.1.6), U_Measuring_2/U_Detect_current (IC1.2.4), U_Measuring_2/U_Measure_current (C26.2.2 U6.2.6), U_Measuring_3/U_Detect_current (IC1.3.4), U_Measuring_3/U_Measure_current (C26.3.2 U6.3.6), U_Measuring_4/U_Detect_current (IC1.4.4), U_Measuring_4/U_Measure_current (C26.4.2 U6.4.6), U_Measuring_5/U_Detect_current (IC1.5.4), U_Measuring_5/U_Measure_current (C26.5.2 U6.5.6), U_Measuring_6/U_Detect_current (IC1.6.4), U_Measuring_6/U_Measure_current (C26.6.2 U6.6.6), U_Measuring_7/U_Detect_current (IC1.7.4), U_Measuring_7/U_Measure_current (C26.7.2 U6.7.6), U_Measuring_8/U_Detect_current (IC1.8.4), U_Measuring_8/U_Measure_current (C26.8.2 U6.8.6)
+15V: DCC_Amplifier_v3.0 (7 pins), power_v3.0 (7 pins)
+24V: power_v3.0 (R6.1), connector_v3.0 (R1.1 R2.1 R3.2)
GND: CAN_v3.0 (5 pins), DCC_Amplifier_v3.0 (11 pins), MCU_v3.0 (29 pins), power_v3.0 (21 pins), connector_v3.0 (12 pins), U_Measuring_1/U_Detect_current (R29.1.1), U_Measuring_1/U_Measure_current (5 pins), U_Measuring_2/U_Detect_current (R29.2.1), U_Measuring_2/U_Measure_current (5 pins), U_Measuring_3/U_Detect_current (R29.3.1), U_Measuring_3/U_Measure_current (5 pins), U_Measuring_4/U_Detect_current (R29.4.1), U_Measuring_4/U_Measure_current (5 pins), U_Measuring_5/U_Detect_current (R29.5.1), U_Measuring_5/U_Measure_current (5 pins), U_Measuring_6/U_Detect_current (R29.6.1), U_Measuring_6/U_Measure_current (5 pins), U_Measuring_7/U_Detect_current (R29.7.1), U_Measuring_7/U_Measure_current (5 pins), U_Measuring_8/U_Detect_current (R29.8.1), U_Measuring_8/U_Measure_current (5 pins)
CAN_H: CAN_v3.0 (D4.1 D5.2 U2.7), connector_v3.0 (P1.1 P1.9 P2.1 R4.2)
CAN_L: CAN_v3.0 (D3.1 D4.2 U2.6), connector_v3.0 (P1.2 P1.10 P2.2 P5.2)
CAN_RX: CAN_v3.0 (U2.4), MCU_v3.0 (U1.22)
CAN_TX: CAN_v3.0 (U2.1), MCU_v3.0 (U1.21)
DCC+: MCU_v3.0 (D8.1 D9.2 U3.7), connector_v3.0 (P1.7 P1.15 P2.7 R5.2)
DCC-: MCU_v3.0 (D7.1 D8.2 U3.6), connector_v3.0 (P1.8 P1.16 P2.8 P6.2)
NetC24.1_2: DCC_Amplifier_v3.0 (U8.10 U8.11), terminal_block_v3.0 (8 pins), U_Measuring_1/U_Detect_current (5 pins), U_Measuring_2/U_Detect_current (5 pins), U_Measuring_3/U_Detect_current (5 pins), U_Measuring_4/U_Detect_current (5 pins), U_Measuring_5/U_Detect_current (5 pins), U_Measuring_6/U_Detect_current (5 pins), U_Measuring_7/U_Detect_current (5 pins), U_Measuring_8/U_Detect_current (5 pins)
NetC27.1_2: MCU_v3.0 (U1.34), U_Measuring_1/U_Measure_current (C27.1.2 D16.1.2 R32.1.2)
NetC27.2_2: MCU_v3.0 (U1.36), U_Measuring_2/U_Measure_current (C27.2.2 D16.2.2 R32.2.2)
NetC27.3_2: MCU_v3.0 (U1.38), U_Measuring_3/U_Measure_current (C27.3.2 D16.3.2 R32.3.2)
NetC27.4_2: MCU_v3.0 (U1.40), U_Measuring_4/U_Measure_current (C27.4.2 D16.4.2 R32.4.2)
NetC27.5_2: MCU_v3.0 (U1.44), U_Measuring_5/U_Measure_current (C27.5.2 D16.5.2 R32.5.2)
NetC27.6_2: MCU_v3.0 (U1.46), U_Measuring_6/U_Measure_current (C27.6.2 D16.6.2 R32.6.2)
NetC27.7_2: MCU_v3.0 (U1.48), U_Measuring_7/U_Measure_current (C27.7.2 D16.7.2 R32.7.2)
NetC27.8_2: MCU_v3.0 (U1.2), U_Measuring_8/U_Measure_current (C27.8.2 D16.8.2 R32.8.2)
NetD12.1_1: U_Measuring_1/U_Detect_current (D12.1.1 D13.1.1 D14.1.2 R27.1.2), U_Measuring_1/U_Measure_current (R31.1.1 U6.1.3)
NetD12.1_2: DCC_Amplifier_v3.0 (U8.22 U8.23), U_Measuring_1/U_Detect_current (D12.1.2 D14.1.1 Q2.1.2), U_Measuring_2/U_Detect_current (D12.2.2 D14.2.1 Q2.2.2), U_Measuring_3/U_Detect_current (D12.3.2 D14.3.1 Q2.3.2), U_Measuring_4/U_Detect_current (D12.4.2 D14.4.1 Q2.4.2), U_Measuring_5/U_Detect_current (D12.5.2 D14.5.1 Q2.5.2), U_Measuring_6/U_Detect_current (D12.6.2 D14.6.1 Q2.6.2), U_Measuring_7/U_Detect_current (D12.7.2 D14.7.1 Q2.7.2), U_Measuring_8/U_Detect_current (D12.8.2 D14.8.1 Q2.8.2)
NetD12.2_1: U_Measuring_2/U_Detect_current (D12.2.1 D13.2.1 D14.2.2 R27.2.2), U_Measuring_2/U_Measure_current (R31.2.1 U6.2.3)
NetD12.3_1: U_Measuring_3/U_Detect_current (D12.3.1 D13.3.1 D14.3.2 R27.3.2), U_Measuring_3/U_Measure_current (R31.3.1 U6.3.3)
NetD12.4_1: U_Measuring_4/U_Detect_current (D12.4.1 D13.4.1 D14.4.2 R27.4.2), U_Measuring_4/U_Measure_current (R31.4.1 U6.4.3)
NetD12.5_1: U_Measuring_5/U_Detect_current (D12.5.1 D13.5.1 D14.5.2 R27.5.2), U_Measuring_5/U_Measure_current (R31.5.1 U6.5.3)
NetD12.6_1: U_Measuring_6/U_Detect_current (D12.6.1 D13.6.1 D14.6.2 R27.6.2), U_Measuring_6/U_Measure_current (R31.6.1 U6.6.3)
NetD12.7_1: U_Measuring_7/U_Detect_current (D12.7.1 D13.7.1 D14.7.2 R27.7.2), U_Measuring_7/U_Measure_current (R31.7.1 U6.7.3)
NetD12.8_1: U_Measuring_8/U_Detect_current (D12.8.1 D13.8.1 D14.8.2 R27.8.2), U_Measuring_8/U_Measure_current (R31.8.1 U6.8.3)
NetD17_1: DCC_Amplifier_v3.0 (D17.1 R33.2 U8.3), MCU_v3.0 (U1.3)
NetIC1.1_3: MCU_v3.0 (U1.35), U_Measuring_1/U_Detect_current (IC1.1.3 R29.1.2)
NetIC1.2_3: MCU_v3.0 (U1.37), U_Measuring_2/U_Detect_current (IC1.2.3 R29.2.2)
NetIC1.3_3: MCU_v3.0 (U1.39), U_Measuring_3/U_Detect_current (IC1.3.3 R29.3.2)
NetIC1.4_3: MCU_v3.0 (U1.41), U_Measuring_4/U_Detect_current (IC1.4.3 R29.4.2)
NetIC1.5_3: MCU_v3.0 (U1.45), U_Measuring_5/U_Detect_current (IC1.5.3 R29.5.2)
NetIC1.6_3: MCU_v3.0 (U1.47), U_Measuring_6/U_Detect_current (IC1.6.3 R29.6.2)
NetIC1.7_3: MCU_v3.0 (U1.1), U_Measuring_7/U_Detect_current (IC1.7.3 R29.7.2)
NetIC1.8_3: MCU_v3.0 (U1.9), U_Measuring_8/U_Detect_current (IC1.8.3 R29.8.2)
NetP8_1: terminal_block_v3.0 (P8.1), U_Measuring_1/U_Measure_current (R31.1.2 U6.1.4)
NetP9_1: terminal_block_v3.0 (P9.1), U_Measuring_2/U_Measure_current (R31.2.2 U6.2.4)
NetP10_1: terminal_block_v3.0 (P10.1), U_Measuring_3/U_Measure_current (R31.3.2 U6.3.4)
NetP11_1: terminal_block_v3.0 (P11.1), U_Measuring_4/U_Measure_current (R31.4.2 U6.4.4)
NetP12_1: terminal_block_v3.0 (P12.1), U_Measuring_5/U_Measure_current (R31.5.2 U6.5.4)
NetP13_1: terminal_block_v3.0 (P13.1), U_Measuring_6/U_Measure_current (R31.6.2 U6.6.4)
NetP14_1: terminal_block_v3.0 (P14.1), U_Measuring_7/U_Measure_current (R31.7.2 U6.7.4)
NetP15_1: terminal_block_v3.0 (P15.1), U_Measuring_8/U_Measure_current (R31.8.2 U6.8.4)
NetR18_1: DCC_Amplifier_v3.0 (U8.5), MCU_v3.0 (R18.1 U1.32)
NetR22_2: DCC_Amplifier_v3.0 (U8.2), MCU_v3.0 (R22.2 U1.31)
NetR23_2: MCU_v3.0 (U1.23), power_v3.0 (R23.2 U5.5)
NetR32_1: DCC_Amplifier_v3.0 (R32.1 U8.32), MCU_v3.0 (U1.24)
NetU3_4: DCC_Amplifier_v3.0 (U7.2 U8.29), MCU_v3.0 (U3.4)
